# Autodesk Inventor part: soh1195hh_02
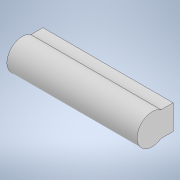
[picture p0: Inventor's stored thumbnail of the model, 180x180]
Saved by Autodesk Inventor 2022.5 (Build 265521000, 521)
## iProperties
Created: 2023-06
Part Number: soh1195hh_02
Material: Generic
Document SubType Name: Modeling
Designer: ImaoCorp
Density: 1 g/cm^3
Appearance: Default
Author: ImaoCorp
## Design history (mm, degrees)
feature "soh1195hh_02"
node "ソリッド1"
